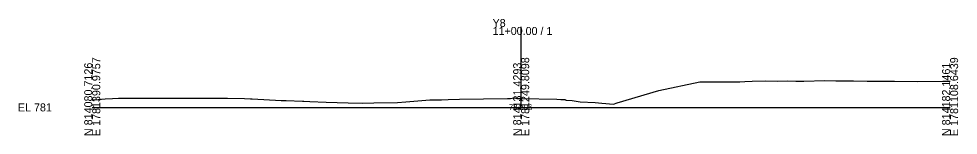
# Model space of a CAD drawing. Extents: x -26 to 303, y -10 to 5036.
# Drawn here: x -25.7 to 302.8, y 990.3 to 1030.9 of the extents above; entities that cross this region are included whole.
import ezdxf

# ---------------------------------------------------------------- set-up
doc = ezdxf.new("R2010")
doc.units = 0
for name, color, linetype in [('Exist Cross Section Cell', 7, 'Continuous'), ('Exist XS Center Line Elevation Label', 7, 'Continuous'), ('Exist XS Ground Line', 7, 'Continuous')]:
    doc.layers.add(name, color=color, linetype=linetype)

msp = doc.modelspace()

# ---------------------------------------------------------------- linework, layer by layer
at = {"layer": 'Exist Cross Section Cell'}
for p, q in [((150, 1000), (150, 1028.07)), ((0, 1000), (150, 1000)), ((150, 1000), (300, 1000))]:
    msp.add_line(p, q, dxfattribs=at)
at = {"layer": 'Exist XS Ground Line'}
for p, q in [((198.14, 1005.9), (212.53, 1008.87)), ((212.53, 1008.87), (213.8, 1008.92)), ((213.8, 1008.92), (216.68, 1008.93)), ((216.68, 1008.93), (226.44, 1008.88)), ((226.44, 1008.88), (228.2, 1009.01)), ((228.2, 1009.01), (230.76, 1009.14)), ((230.76, 1009.14), (235.58, 1009.22)), ((235.58, 1009.22), (239.74, 1009.17)), ((239.74, 1009.17), (243.03, 1009.22)), ((243.03, 1009.22), (246.1, 1009.2)), ((246.1, 1009.2), (248.8, 1009.19)), ((248.8, 1009.19), (256.16, 1009.36)), ((256.16, 1009.36), (260.04, 1009.29)), ((260.04, 1009.29), (266.27, 1009.26)), ((266.27, 1009.26), (271.05, 1009.17)), ((271.05, 1009.17), (276.73, 1009.15)), ((276.73, 1009.15), (279.48, 1009.14)), ((279.48, 1009.14), (280.6, 1009.12)), ((280.6, 1009.12), (288.71, 1009.01)), ((288.71, 1009.01), (297.43, 1009.13)), ((297.43, 1009.13), (299.41, 1009.15)), ((299.41, 1009.15), (300, 1009.16)), ((183.57, 1001.65), (198.14, 1005.9)), ((0, 1002.59), (0.75, 1002.65)), ((0.75, 1002.65), (4.53, 1002.95)), ((4.53, 1002.95), (7.13, 1003.08)), ((7.13, 1003.08), (9.14, 1003.17)), ((9.14, 1003.17), (20.94, 1003.2)), ((20.94, 1003.2), (27.57, 1003.21)), ((27.57, 1003.21), (35.58, 1003.2)), ((35.58, 1003.2), (46.9, 1003.21)), ((46.9, 1003.21), (47.32, 1003.22)), ((47.32, 1003.22), (53.26, 1003.05)), ((53.26, 1003.05), (55.34, 1002.98)), ((55.34, 1002.98), (55.95, 1002.94)), ((55.95, 1002.94), (66.12, 1002.44)), ((66.12, 1002.44), (67.85, 1002.38)), ((67.85, 1002.38), (73.52, 1002.19)), ((73.52, 1002.19), (73.95, 1002.17)), ((73.95, 1002.17), (76.04, 1002.11)), ((76.04, 1002.11), (81.79, 1001.83)), ((109.66, 1001.96), (118.11, 1002.6)), ((118.11, 1002.6), (121.61, 1002.64)), ((121.61, 1002.64), (122.11, 1002.65)), ((122.11, 1002.65), (124.43, 1002.8)), ((124.43, 1002.8), (128.39, 1002.87)), ((128.39, 1002.87), (145.24, 1003.09)), ((145.24, 1003.09), (146.21, 1003.15)), ((146.21, 1003.15), (147.4, 1003.28)), ((147.4, 1003.28), (148.83, 1003.13)), ((148.83, 1003.13), (149.64, 1003.06)), ((149.64, 1003.06), (150, 1003.06)), ((150, 1003.06), (162.51, 1002.84)), ((162.51, 1002.84), (163.86, 1002.81)), ((163.86, 1002.81), (165.52, 1002.7)), ((165.52, 1002.7), (165.62, 1002.58)), ((165.62, 1002.58), (167.82, 1002.37)), ((167.82, 1002.37), (170.67, 1001.98)), ((81.79, 1001.83), (89.47, 1001.63)), ((89.47, 1001.63), (94.61, 1001.46)), ((94.61, 1001.46), (98.42, 1001.59)), ((98.42, 1001.59), (106.73, 1001.75)), ((106.73, 1001.75), (109.66, 1001.96)), ((170.67, 1001.98), (175.92, 1001.7)), ((175.92, 1001.7), (178.21, 1001.49)), ((178.21, 1001.49), (182.28, 1001.16)), ((182.28, 1001.16), (183.57, 1001.65))]:
    msp.add_line(p, q, dxfattribs=at)

# ---------------------------------------------------------------- texts
at = {"layer": 'Exist Cross Section Cell'}
for s, p in [('Y8', (140, 1028.07)), ('11+00.00 / 1', (140, 1025.27)), ('EL 781', (-26, 998.6))]:
    msp.add_text(s, height=2.8, dxfattribs=at).set_placement(p)
for s, p in [('N 814080.7126', (0, 990)), ('E 1781390.9757', (2.8, 990)), ('N 814131.4293', (150, 990)), ('E 1781249.8098', (152.8, 990)), ('N 814182.1461', (300, 990)), ('E 1781108.6439', (302.8, 990))]:
    msp.add_text(s, height=2.8, rotation=90, dxfattribs=at).set_placement(p)
at = {"layer": 'Exist XS Center Line Elevation Label'}
msp.add_text('784.06', height=2, dxfattribs=at).set_placement((145.73, 999.06))

doc.saveas('drawing.dxf')
